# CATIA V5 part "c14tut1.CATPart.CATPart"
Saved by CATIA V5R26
Part number: Part1
Bounding box of the stored display mesh (mm): x 0 to 46, y -104 to 104, z 0 to 68
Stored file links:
  D:\_Deepak\CATIA\CATIA V5 2015 Parts Files\Tutorial Files\Tutorials\c14_catia_v5_6r2016_tut\c14tut1\c14tut1.CATPart.CATPart
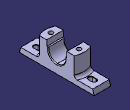
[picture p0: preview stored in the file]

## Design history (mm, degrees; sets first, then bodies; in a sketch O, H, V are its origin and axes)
Body1 (main body)
  Sketch1 on yz-plane, origin (0, 0, 0), H (0, 1, 0), V (0, 0, 1)
    axis line L1 (0, -39.4814) -> (0, 63.0107)
    point P1 (0, -39.4814)
    line L2 (0, 0) -> (104, 0)
    point P3 (104, 0)
    line L3 (104, 0) -> (100, 14)
    point P4 (100, 14)
    line L4 (100, 14) -> (54, 14)
    point P5 (54, 14)
    line L5 (54, 14) -> (54, 68)
    point P6 (54, 68)
    line L6 (54, 68) -> (28, 68)
    point P7 (28, 68)
    line L7 (28, 68) -> (28, 52)
    point P8 (28, 52)
    line L8 (28, 52) -> (23.6643, 52)
    point P9 (23.6643, 52)
    arc A1 centre (0, 48) radius 24 from (23.6643, 52) to (0, 24) cw
    point P10 (0, 48)
    point P11 (0, 24)
    point P12 (-104, 0)
    point P13 (0, 0)
    line L9 (0, 0) -> (-104, 0)
    point P14 (0, 24)
    point P15 (-23.6643, 52)
    point P16 (0, 48)
    arc A2 centre (0, 48) radius 24 from (-23.6643, 52) to (0, 24) ccw
    point P17 (-54, 68)
    point P18 (-28, 68)
    point P19 (-28, 52)
    line L10 (-54, 68) -> (-28, 68)
    line L11 (-28, 68) -> (-28, 52)
    line L12 (-28, 52) -> (-23.6643, 52)
    point P20 (-54, 14)
    line L13 (-54, 14) -> (-54, 68)
    point P21 (-100, 14)
    line L14 (-100, 14) -> (-54, 14)
    line L15 (-104, 0) -> (-100, 14)
    distance P3 P12 = 208
    length L3 V = 14
    distance L5 L13 = 108
    distance P18 P7 = 56
    distance P19 P18 = 16
    distance P15 P16 V = 4
    length L15 H = 4
    radius A1 = 24
    distance L6 L2 = 68
    coincidence: P1 V, P10 L1, L1 P11, O P13, P11 P14
    vertical: L1 V, L5 V, L7 V
    horizontal: L2 H, L4 H, L6 H, L8 H
    symmetry: P3 P12 L1, O P13 L1, L2 L9 L1, P11 P14 L1, P9 P15 L1, A1 A2 L1, P6 P17 L1, P7 P18 L1, P8 P19 L1, L6 L10 L1, L7 L11 L1, L8 L12 L1, P5 P20 L1, L5 L13 L1, P4 P21 L1, L4 L14 L1, L3 L15 L1
  Pad1: profile Sketch1, direction (1, 0, 0), length 46
  Sketch2 on face of Pad1, origin (0, 0, 14), H (1, 0, 0), V (0, 1, 0)
    arc A1 centre (23, 4) radius 50 from (0, 48.3959) to (46, 48.3959) cw
    point P2 (0, 48.3959)
    point P3 (46, 48.3959)
    reference projected line E1 (46, 54) -> (46, 28) from edge [face of Pad1 | face of Pad1]
    construction line L1 (46, 48.3959) -> (0, 48.3959)
    reference projected line E2 (0, 54) -> (46, 54) from edge [face of Pad1 | face of Pad1]
    axis line L2 (-10.6771, 0) -> (51.171, 0)
    point P4 (-10.6771, 0)
    point P6 (46, -48.3959)
    point P7 (0, -48.3959)
    arc A2 centre (23, -4) radius 50 from (0, -48.3959) to (46, -48.3959) ccw
    line L3 (0, -48.3959) -> (0, 48.3959)
    line L4 (46, 48.3959) -> (46, -48.3959)
    radius A1 = 50
    coincidence: P2 V, P3 E1, P4 H
    horizontal: L1 H, L2 H
    tangency: A1 E2
    symmetry: P3 P6 L2, P2 P7 L2, A1 A2 L2
    vertical: L3 V, L4 V
  Pocket1: profile Sketch2, direction (0, 0, 1), through (limit type 3), outer side
  Sketch3 on face of Pad1, origin (0, 0, 0), H (1, 0, 0), V (0, -1, 0)
    axis line L1 (46, -104) -> (0, 104)
    point P1 (46, -104)
    point P2 (0, 104)
    reference projected point E1 (46, -104) from vertex [face of Pad1 | face of Pad1 | face of Pad1]
    reference projected point E2 (0, 104) from vertex [face of Pad1 | face of Pad1 | face of Pad1]
    point P3 (23, 0)
    line L2 (40.5, 97.5) -> (40.5, -97.5)
    line L3 (40.5, -97.5) -> (5.5, -97.5)
    line L4 (5.5, -97.5) -> (5.5, 97.5)
    line L5 (5.5, 97.5) -> (40.5, 97.5)
    length L3 = 35
    length L2 = 195
    coincidence: P1 E1, P2 E2
    midpoint: P3 L1
    vertical: L2 V, L4 V
    horizontal: L3 H, L5 H
    equidistance: L2 L4 P3, L3 L5 P3
  Pocket2: profile Sketch3, direction (0, 0, 1), length 2
  Sketch4 on face of Pad1, origin (0, 0, 0), H (1, 0, 0), V (0, -1, 0)
    point P1 (23, 39)
    line L1 (36, 52) -> (36, 26)
    line L2 (36, 26) -> (10, 26)
    line L3 (10, 26) -> (10, 52)
    line L4 (10, 52) -> (36, 52)
    construction line L5 (40.5, 0) -> (5.5, 0)
    point P6 (40.5, 0)
    point P7 (5.5, 0)
    reference projected line E1 (40.5, -97.5) -> (40.5, 0) from edge [face of Pad1 | face of Pocket2]
    reference projected line E2 (5.5, 0) -> (5.5, -97.5) from edge [face of Pad1 | face of Pocket2]
    axis line L6 (23, 39) -> (23, 0)
    point P8 (23, 0)
    reference intersected line E3 (0, 104) -> (46, 104) from face of Pad1
    length L3 = 26
    length L4 = 26
    distance L2 E3 = 78
    vertical: L1 V, L3 V, L6 V
    horizontal: L2 H, L4 H, L5 H
    equidistance: L1 L3 P1, L2 L4 P1
    coincidence: P6 H, E1 P6, P7 E2, P8 L5
    midpoint: P8 L5
  Pocket3: profile Sketch4, direction (0, 0, 1), length 10
  Sketch5 on face of Pad1, origin (24.629, 46.0353, 68), H (1, 0, 0), V (0, 1, 0)
    point P1 (-1.629, -85.0353)
    axis line L1 (11.371, -98.0353) -> (-14.629, -72.0353)
    point P2 (11.371, -98.0353)
    point P3 (-14.629, -72.0353)
    reference projected point E1 (11.371, -98.0353) from vertex [face of Pocket3 | face of Pocket3 | face of Pocket3]
    reference projected point E2 (-14.629, -72.0353) from vertex [face of Pocket3 | face of Pocket3 | face of Pocket3]
    coincidence: P2 E1, P3 E2
    midpoint: P1 L1
  Hole1: placed by Sketch5, at (23, -39, 68) direction (0, 0, -1), diameter 12, through (limit type 3)
  Sketch6 on face of Pad1, origin (0, 0, 14), H (1, 0, 0), V (0, 1, 0)
    construction line L1 (23, -71) -> (23, -81)
    point P2 (23, -81)
    line L2 (29, -71) -> (29, -81)
    line L3 (17, -81) -> (17, -71)
    arc A1 centre (23, -81) radius 6 from (29, -81) to (17, -81) cw
    arc A2 centre (23, -71) radius 6 from (17, -71) to (29, -71) cw
    reference projected line E1 (46, -54) -> (46, -100) from edge of Pad1
    reference projected line E2 (0, -104) -> (46, -104) from edge [face of Pad1 | face of Pad1]
    distance L1 E1 = 23
    distance P2 E2 = 23
    radius A1 = 6
    length L1 = 10
    vertical: L1 V
    tangency: A1 L2, A2 L2, A1 L3, A2 L3
    parallelism: L1 L2
  Pocket4: profile Sketch6, direction (0, 0, -1), through (limit type 3)
  Mirror1: of Pocket3, Sketch4, Hole1, Pocket4, Sketch6, about zx-plane
  Fillet1: radius 8, on 2 edges
  Chamfer1: length 1, angle 45, on 2 edges
  Chamfer2: length 2, angle 45, on edge [face of Pad1 | face of Pad1] (x2)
